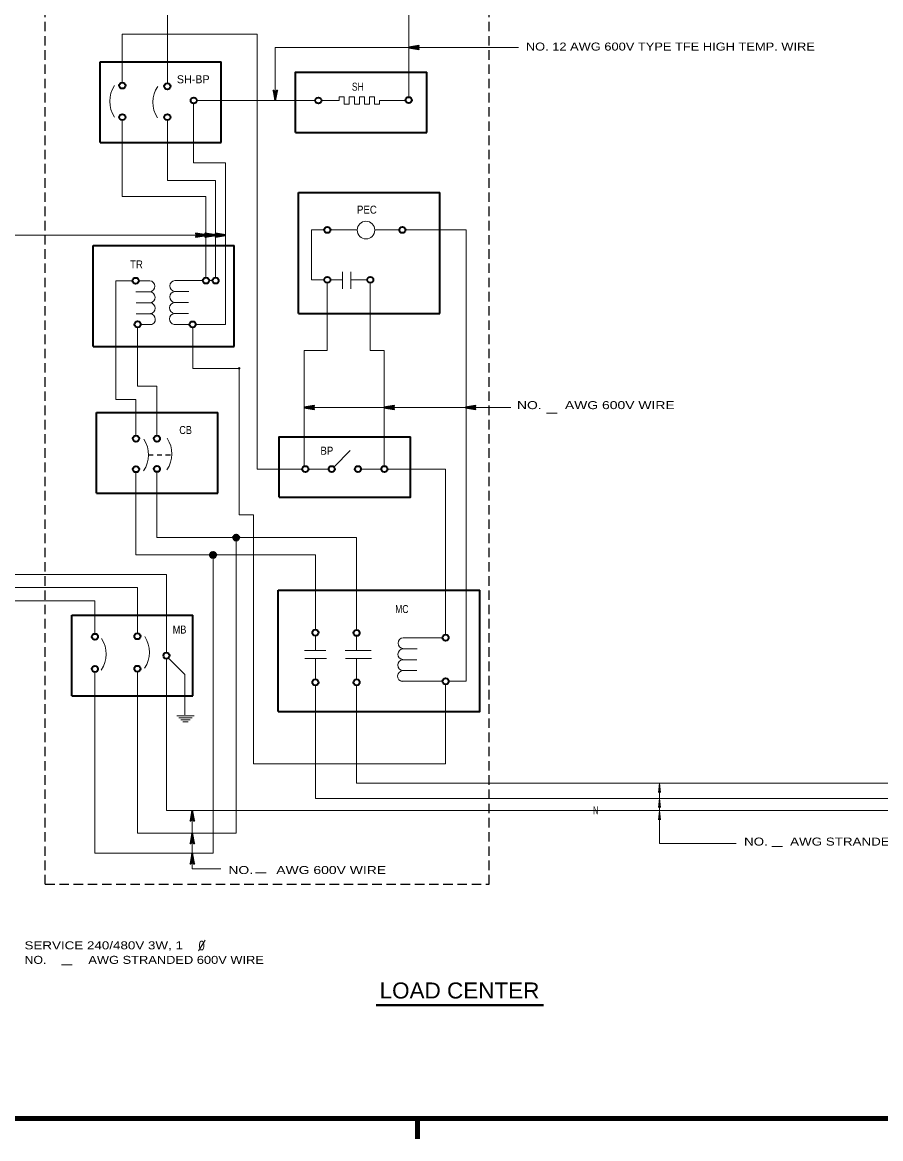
# Model space of a CAD drawing. Extents: x 312583 to 312853, y 144420 to 144585.
# Drawn here: x 312689.8 to 312771.3, y 144421.2 to 144527.2 of the extents above; entities that cross this region are included whole.
import ezdxf
from ezdxf.enums import TextEntityAlignment as Align

# ---------------------------------------------------------------- set-up
doc = ezdxf.new("R2010")
doc.units = 0
doc.header["$LTSCALE"] = 0.3
doc.header["$PDMODE"] = 32
doc.header["$PDSIZE"] = 0.15
doc.linetypes.add('MEDIUM_DASHED', pattern=[4.5, 3, -1.5])
doc.linetypes.add('SHORT_DASHED', pattern=[2.7, 1.5, -1.2])
doc.layers.add('1', color=7, linetype='Continuous', lineweight=13)

msp = doc.modelspace()

# ---------------------------------------------------------------- linework, layer by layer
at = {"layer": '1', "linetype": 'MEDIUM_DASHED', "lineweight": 25}
for p, q in [((312691.9957, 144445.3243), (312691.9957, 144533.491)), ((312734.1624, 144445.3243), (312734.1624, 144533.491)), ((312691.9957, 144445.3243), (312734.1624, 144445.3243))]:
    msp.add_line(p, q, dxfattribs=at)
at = {"layer": '1'}
for p, q in [((312703.5954, 144529.466), (312703.5954, 144521.4006)), ((312726.511, 144529.466), (312726.511, 144520.0896)), ((312699.3174, 144526.0543), (312712.1284, 144526.0543)), ((312699.3174, 144526.0543), (312699.3174, 144521.4773)), ((312712.1284, 144526.0543), (312712.1284, 144484.754)), ((312726.511, 144524.7816), (312736.9343, 144524.7816)), ((312719.91, 144519.7523), (312719.91, 144520.1126)), ((312719.91, 144520.1126), (312720.393, 144520.1126)), ((312720.393, 144519.392), (312720.393, 144520.1126)), ((312720.8684, 144519.392), (312720.8684, 144520.1126)), ((312720.8684, 144520.1126), (312721.3514, 144520.1126)), ((312721.3514, 144519.392), (312721.3514, 144520.1126)), ((312721.8267, 144519.392), (312721.8267, 144520.1126)), ((312721.8267, 144520.1126), (312722.3097, 144520.1126)), ((312722.3097, 144519.392), (312722.3097, 144520.1126)), ((312722.785, 144519.392), (312722.785, 144520.1126)), ((312722.785, 144520.1126), (312723.268, 144520.1126)), ((312723.268, 144519.392), (312723.268, 144520.1126)), ((312706.3937, 144519.7523), (312717.587, 144519.7523)), ((312718.2234, 144519.7523), (312719.91, 144519.7523)), ((312720.393, 144519.392), (312720.8684, 144519.392)), ((312721.3514, 144519.392), (312721.8267, 144519.392)), ((312722.3097, 144519.392), (312722.785, 144519.392)), ((312723.268, 144519.392), (312723.7434, 144519.392)), ((312723.7434, 144519.392), (312723.7434, 144519.7523)), ((312723.7434, 144519.7523), (312726.235, 144519.7523)), ((312699.3174, 144517.874), (312699.3174, 144510.652)), ((312703.5954, 144517.9046), (312703.5954, 144512.1623)), ((312703.5954, 144512.1623), (312708.1724, 144512.1623)), ((312708.1724, 144512.1623), (312708.1724, 144502.9623)), ((312699.3174, 144510.652), (312707.26, 144510.652)), ((312707.26, 144510.652), (312707.26, 144502.9776)), ((312717.288, 144507.4626), (312717.288, 144502.7246)), ((312718.461, 144507.4626), (312717.288, 144507.4626)), ((312721.6197, 144507.4626), (312719.0667, 144507.4626)), ((312725.6217, 144507.4626), (312723.291, 144507.4626)), ((312731.962, 144507.4626), (312726.2197, 144507.4626)), ((312731.962, 144464.5983), (312731.962, 144507.4626)), ((312708.1647, 144506.9566), (312709.1307, 144506.9566)), ((312720.2167, 144501.866), (312720.2167, 144503.476)), ((312721.0217, 144501.866), (312721.0217, 144503.476)), ((312698.6887, 144502.6326), (312698.6887, 144491.3703)), ((312700.291, 144502.6326), (312698.6887, 144502.6326)), ((312701.924, 144502.6326), (312700.866, 144502.6326)), ((312704.316, 144502.6556), (312706.961, 144502.6556)), ((312707.5054, 144502.6556), (312707.881, 144502.6556)), ((312717.288, 144502.7246), (312718.4917, 144502.7246)), ((312718.76, 144502.441), (312718.76, 144496.001)), ((312719.059, 144502.7246), (312720.2167, 144502.7246)), ((312721.0217, 144502.7246), (312722.5627, 144502.7246)), ((312722.8617, 144502.4256), (312722.8617, 144496.001)), ((312701.9547, 144501.59), (312700.613, 144501.59)), ((312701.9394, 144501.59), (312700.613, 144501.59)), ((312704.2854, 144501.613), (312705.627, 144501.613)), ((312704.3007, 144501.613), (312705.627, 144501.613)), ((312701.97, 144500.5473), (312700.6284, 144500.5473)), ((312701.9547, 144500.5473), (312700.6284, 144500.5473)), ((312704.27, 144500.5703), (312705.6117, 144500.5703)), ((312704.2854, 144500.5703), (312705.6117, 144500.5703)), ((312701.9854, 144499.5046), (312700.6437, 144499.5046)), ((312701.97, 144499.5046), (312700.6437, 144499.5046)), ((312704.2547, 144499.5276), (312705.5964, 144499.5276)), ((312704.27, 144499.5276), (312705.5964, 144499.5276)), ((312702.108, 144498.4926), (312701.0577, 144498.4926)), ((312704.2394, 144498.485), (312705.581, 144498.485)), ((312709.1307, 144498.485), (312706.2787, 144498.485)), ((312722.8617, 144496.001), (312724.188, 144496.001)), ((312724.188, 144485.0223), (312724.188, 144496.001)), ((312702.5987, 144492.6276), (312702.5987, 144487.928)), ((312698.6887, 144491.3703), (312700.613, 144491.3703)), ((312700.613, 144491.3703), (312700.613, 144487.9126)), ((312724.1574, 144490.6113), (312716.575, 144490.6113)), ((312739.5827, 144490.0516), (312740.6177, 144490.0516)), ((312719.4194, 144484.9763), (312720.9527, 144486.5096)), ((312700.613, 144484.4243), (312700.613, 144476.6043)), ((312702.5987, 144484.4933), (312702.5987, 144478.245)), ((312712.1284, 144484.754), (312716.3987, 144484.754)), ((312716.9584, 144484.754), (312718.898, 144484.754)), ((312721.9494, 144484.754), (312723.9044, 144484.754)), ((312724.5177, 144484.754), (312730.007, 144484.754)), ((312730.007, 144484.754), (312730.007, 144468.9836)), ((312710.1274, 144478.245), (312710.1274, 144450.185)), ((312721.5584, 144478.245), (312721.5584, 144469.5356)), ((312700.613, 144476.6043), (312717.656, 144476.6043)), ((312707.9347, 144476.6043), (312707.9347, 144448.2913)), ((312717.656, 144476.6043), (312717.656, 144469.4743)), ((312703.511, 144474.7566), (312672.6987, 144474.7566)), ((312703.511, 144474.7566), (312703.511, 144467.32)), ((312700.751, 144473.4916), (312675.9417, 144473.4916)), ((312700.751, 144469.1906), (312700.751, 144473.4916)), ((312696.7184, 144472.2266), (312678.7324, 144472.2266)), ((312696.7184, 144469.114), (312696.7184, 144472.2266)), ((312717.656, 144468.93), (312717.656, 144467.5193)), ((312721.5584, 144468.93), (312721.5584, 144467.5193)), ((312725.9897, 144468.7383), (312729.6774, 144468.7383)), ((312716.6287, 144467.5193), (312718.6374, 144467.5193)), ((312720.4774, 144467.5193), (312722.9537, 144467.5193)), ((312725.959, 144467.6956), (312727.3007, 144467.6956)), ((312725.9744, 144467.6956), (312727.3007, 144467.6956)), ((312703.511, 144466.7603), (312703.511, 144452.3163)), ((312705.259, 144465.2423), (312703.6797, 144466.8216)), ((312716.6517, 144466.7756), (312718.6987, 144466.7756)), ((312717.656, 144466.7756), (312717.656, 144464.79)), ((312720.508, 144466.7756), (312722.9767, 144466.7756)), ((312721.5584, 144466.7756), (312721.5584, 144464.8206)), ((312725.9437, 144466.653), (312727.2854, 144466.653)), ((312725.959, 144466.653), (312727.2854, 144466.653)), ((312696.7184, 144448.2913), (312696.7184, 144465.4646)), ((312700.751, 144450.185), (312700.751, 144465.4646)), ((312705.259, 144465.2423), (312705.259, 144461.4166)), ((312725.9284, 144465.6103), (312727.27, 144465.6103)), ((312725.9437, 144465.6103), (312727.27, 144465.6103)), ((312717.656, 144464.1843), (312717.656, 144453.4816)), ((312721.5584, 144464.1536), (312721.5584, 144454.9153)), ((312725.8057, 144464.5983), (312729.708, 144464.5983)), ((312730.007, 144456.7553), (312730.007, 144464.2993)), ((312730.3367, 144464.5983), (312731.962, 144464.5983)), ((312704.4924, 144461.3246), (312706.1407, 144461.3246)), ((312704.684, 144461.133), (312705.949, 144461.133)), ((312704.8757, 144460.9336), (312705.7574, 144460.9336)), ((312705.0674, 144460.742), (312705.5657, 144460.742)), ((312711.768, 144456.7553), (312730.007, 144456.7553)), ((312721.5584, 144454.9153), (312776.954, 144454.9153)), ((312750.3234, 144454.9153), (312750.216, 144454.049)), ((312750.216, 144454.049), (312750.3234, 144454.325)), ((312750.3234, 144454.9153), (312750.4307, 144454.049)), ((312750.4307, 144454.049), (312750.3234, 144454.325)), ((312750.3234, 144453.474), (312750.216, 144452.6076)), ((312750.3234, 144453.474), (312750.4307, 144452.6076)), ((312703.511, 144452.3163), (312737.4437, 144452.3163)), ((312705.9644, 144450.162), (312705.9644, 144452.3163)), ((312721.6236, 144452.3163), (312795.6913, 144452.3163)), ((312750.216, 144452.6076), (312750.3234, 144452.8836)), ((312750.3234, 144452.3086), (312750.216, 144451.4423)), ((312750.4307, 144452.6076), (312750.3234, 144452.8836)), ((312750.3234, 144452.3086), (312750.4307, 144451.4423)), ((312750.216, 144451.4423), (312750.3234, 144451.7183)), ((312750.4307, 144451.4423), (312750.3234, 144451.7183)), ((312710.1274, 144450.185), (312700.751, 144450.185)), ((312757.599, 144449.1883), (312750.3234, 144449.1883)), ((312760.9877, 144448.9046), (312761.992, 144448.9046)), ((312707.9347, 144448.2913), (312696.7184, 144448.2913)), ((312708.663, 144446.7886), (312705.9644, 144446.7886)), ((312711.9674, 144446.4206), (312712.9717, 144446.4206)), ((312707.1895, 144440.0218), (312706.5531, 144439.0021)), ((312693.529, 144437.6576), (312694.564, 144437.6576))]:
    msp.add_line(p, q, dxfattribs=at)
at = {"layer": '1', "lineweight": 35}
for p, q in [((312697.2167, 144523.44), (312708.7167, 144523.44)), ((312697.2167, 144515.7733), (312697.2167, 144523.44)), ((312708.7167, 144515.7733), (312708.7167, 144523.44)), ((312728.2284, 144516.7086), (312728.2284, 144522.4586)), ((312697.2167, 144515.7733), (312708.7167, 144515.7733)), ((312715.77, 144516.7086), (312728.2284, 144516.7086)), ((312716.0614, 144511.0276), (312729.478, 144511.0276)), ((312716.0614, 144499.5276), (312716.0614, 144511.0276)), ((312729.478, 144499.5276), (312729.478, 144511.0276)), ((312696.5344, 144505.9753), (312709.951, 144505.9753)), ((312696.5344, 144496.392), (312696.5344, 144505.9753)), ((312709.951, 144496.392), (312709.951, 144505.9753)), ((312716.0614, 144499.5276), (312729.478, 144499.5276)), ((312696.5344, 144496.392), (312709.951, 144496.392)), ((312696.8717, 144490.1283), (312708.3717, 144490.1283)), ((312696.8717, 144482.4616), (312696.8717, 144490.1283)), ((312708.3717, 144482.4616), (312708.3717, 144490.1283)), ((312696.8717, 144482.4616), (312708.3717, 144482.4616)), ((312714.1064, 144473.2463), (312733.273, 144473.2463)), ((312714.1064, 144461.7463), (312714.1064, 144473.2463)), ((312694.5257, 144470.8773), (312706.0257, 144470.8773)), ((312694.5257, 144463.2106), (312694.5257, 144470.8773)), ((312706.0257, 144463.2106), (312706.0257, 144470.8773)), ((312694.5257, 144463.2106), (312706.0257, 144463.2106))]:
    msp.add_line(p, q, dxfattribs=at)
at = {"layer": '1', "linetype": 'SHORT_DASHED', "lineweight": 25}
msp.add_line((312701.809, 144486.0956), (312703.994, 144486.0956), dxfattribs=at)
at = {"layer": '1', "lineweight": 40}
msp.add_line((312723.4358, 144433.8433), (312739.3103, 144433.8433), dxfattribs=at)
at = {"layer": '1', "lineweight": 158}
for p, q in [((312616.5, 144423.0846), (312849, 144423.0846)), ((312727.35, 144421.1646), (312727.35, 144423.0846))]:
    msp.add_line(p, q, dxfattribs=at)
at = {"layer": '1'}
for points in [[(312726.511, 144524.7816), (312713.8457, 144524.7816), (312713.8457, 144519.7523)], [(312706.0794, 144519.4226), (312706.0794, 144513.8413), (312709.1307, 144513.8413), (312709.1307, 144498.485)], [(312688.4557, 144506.9566), (312707.2677, 144506.9566), (312708.1647, 144506.9566)], [(312700.7664, 144498.2013), (312700.7664, 144492.6276), (312702.5987, 144492.6276)], [(312706.0104, 144498.2013), (312706.0104, 144494.3143), (312710.411, 144494.3143)], [(312716.575, 144484.961), (312716.575, 144496.001), (312718.76, 144496.001)], [(312710.411, 144494.3143), (312710.411, 144480.407), (312711.768, 144480.407), (312711.768, 144456.7553)], [(312736.217, 144490.6113), (312731.893, 144490.6113), (312724.1574, 144490.6113)], [(312702.5987, 144478.245), (312708.3104, 144478.245), (312721.5584, 144478.245)], [(312750.3234, 144449.1883), (312750.3234, 144452.3086), (312750.3234, 144453.474), (312750.3234, 144454.9153)], [(312717.656, 144453.4816), (312744.0946, 144453.4816), (312778.9166, 144453.4816)], [(312705.9644, 144446.7886), (312705.9644, 144448.2376), (312705.9644, 144450.162)]]:
    msp.add_lwpolyline(points, dxfattribs=at)
at = {"layer": '1', "lineweight": 35}
for points in [[(312726.511, 144524.7816), (312727.477, 144524.6206), (312727.155, 144524.7816), (312727.477, 144524.9426)], [(312713.8457, 144519.7523), (312714.0067, 144520.7183), (312713.8457, 144520.3963), (312713.6847, 144520.7183)], [(312707.2677, 144506.9566), (312706.3017, 144507.1176), (312706.6237, 144506.9566), (312706.3017, 144506.7956)], [(312708.1647, 144506.9566), (312707.1987, 144507.1176), (312707.5207, 144506.9566), (312707.1987, 144506.7956)], [(312709.1307, 144506.9566), (312708.1647, 144507.1176), (312708.4867, 144506.9566), (312708.1647, 144506.7956)], [(312716.575, 144490.6113), (312717.541, 144490.4503), (312717.219, 144490.6113), (312717.541, 144490.7723)], [(312724.1574, 144490.6113), (312725.1234, 144490.4503), (312724.8014, 144490.6113), (312725.1234, 144490.7723)], [(312731.893, 144490.6113), (312732.859, 144490.4503), (312732.537, 144490.6113), (312732.859, 144490.7723)], [(312705.9644, 144452.3163), (312705.8034, 144451.3503), (312705.9644, 144451.6723), (312706.1254, 144451.3503)], [(312705.9644, 144450.162), (312705.8034, 144449.196), (312705.9644, 144449.518), (312706.1254, 144449.196)], [(312705.9644, 144448.2376), (312705.8034, 144447.2716), (312705.9644, 144447.5936), (312706.1254, 144447.2716)]]:
    msp.add_lwpolyline(points, close=True, dxfattribs=at)
for points in [[(312715.77, 144516.7086), (312715.77, 144522.4586), (312728.2284, 144522.4586)], [(312714.2214, 144482.0783), (312714.2214, 144487.8283), (312726.6797, 144487.8283)], [(312714.2214, 144482.0783), (312726.6797, 144482.0783), (312726.6797, 144487.8283)], [(312714.1064, 144461.7463), (312733.273, 144461.7463), (312733.273, 144473.2463)]]:
    msp.add_lwpolyline(points, dxfattribs=at)
for centre, radius in [((312699.3171, 144521.1706), 0.2897), ((312703.5951, 144521.1016), 0.2897), ((312706.1024, 144519.7525), 0.2897), ((312717.932, 144519.7521), 0.2897), ((312726.5108, 144519.7906), 0.2897), ((312699.3176, 144518.173), 0.2897), ((312703.5956, 144518.173), 0.2897), ((312718.783, 144507.4624), 0.2897), ((312725.913, 144507.4629), 0.2897), ((312707.2598, 144502.6556), 0.2897), ((312708.1721, 144502.6556), 0.2897), ((312718.783, 144502.7244), 0.2897), ((312722.8617, 144502.7244), 0.2897), ((312700.5824, 144502.6329), 0.2897), ((312700.7664, 144498.4929), 0.2897), ((312705.9874, 144498.4852), 0.2897), ((312700.6128, 144487.6443), 0.2897), ((312702.5985, 144487.6443), 0.2897), ((312700.6133, 144484.7386), 0.2897), ((312702.5989, 144484.7693), 0.2897), ((312716.6977, 144484.7542), 0.2897), ((312719.2047, 144484.7542), 0.2897), ((312721.6887, 144484.7542), 0.2897), ((312724.2034, 144484.7542), 0.2897), ((312710.1276, 144478.245), 0.2897), ((312710.1274, 144478.245), 0.23), ((312710.1274, 144478.245), 0.1533), ((312710.1274, 144478.245), 0.0767), ((312707.9349, 144476.6043), 0.2897), ((312707.9347, 144476.6043), 0.23), ((312707.9347, 144476.6043), 0.1533), ((312707.9347, 144476.6043), 0.0767), ((312696.7181, 144468.8303), 0.2897), ((312700.7508, 144468.8763), 0.2897), ((312717.6558, 144469.2213), 0.2897), ((312721.5581, 144469.1983), 0.2897), ((312730.0068, 144468.7383), 0.2897), ((312703.5113, 144467.0363), 0.2897), ((312696.7186, 144465.7713), 0.2897), ((312700.7513, 144465.7866), 0.2897), ((312717.6563, 144464.4986), 0.2897), ((312721.5586, 144464.4986), 0.2897), ((312730.0073, 144464.5983), 0.2897)]:
    msp.add_circle(centre, radius, dxfattribs=at)
at = {"layer": '1'}
msp.add_circle((312722.4554, 144507.4473), 0.8385, dxfattribs=at)
for centre, radius, start, end in [((312700.8046, 144519.6642), 2.6791, 145.78717, 213.62519), ((312704.8909, 144519.5876), 2.6791, 145.78717, 213.62519), ((312701.8862, 144502.1127), 0.5203, 277.35858, 85.77701), ((312704.3539, 144502.1357), 0.5203, 94.22299, 262.64142), ((312701.9015, 144501.07), 0.5203, 277.35858, 85.77701), ((312704.3385, 144501.093), 0.5203, 94.22299, 262.64142), ((312701.9169, 144500.0273), 0.5203, 277.35858, 85.77701), ((312704.3232, 144500.0503), 0.5203, 94.22299, 262.64142), ((312701.9322, 144498.9847), 0.5203, 277.35858, 85.77701), ((312704.3079, 144499.0077), 0.5203, 94.22299, 262.64142), ((312699.1258, 144486.0994), 2.6791, 325.78717, 33.62519), ((312701.3415, 144486.1914), 2.6791, 325.78717, 33.62519), ((312695.1085, 144467.178), 2.6791, 325.78717, 33.62519), ((312699.2178, 144467.3544), 2.6791, 325.78717, 33.62519), ((312726.0275, 144468.2183), 0.5203, 94.22299, 262.64142), ((312726.0122, 144467.1757), 0.5203, 94.22299, 262.64142), ((312725.9969, 144466.133), 0.5203, 94.22299, 262.64142), ((312725.9815, 144465.0903), 0.5203, 94.22299, 262.64142)]:
    msp.add_arc(centre, radius, start, end, dxfattribs=at)
msp.add_point((312710.411, 144494.3143), dxfattribs=at)

# ---------------------------------------------------------------- texts
for s, height, width, p in [('NO. 12 AWG 600V TYPE TFE HIGH TEMP. WIRE', 0.76, 1.2, (312737.6337, 144524.4951)), ('SH', 0.76, 0.8, (312721.1126, 144520.6827)), ('PEC', 0.76, 0.9, (312721.6018, 144509.0064)), ('TR', 0.76, 0.9, (312700.0528, 144503.8046)), ('NO.      AWG 600V WIRE', 0.76, 1.3, (312736.792, 144490.4455)), ('CB', 0.76, 0.85, (312704.7291, 144488.0803)), ('BP', 0.76, 0.9, (312718.1319, 144486.1158)), ('MC', 0.76, 0.8, (312725.2298, 144471.0776)), ('MB', 0.76, 0.85, (312704.1061, 144469.1312)), ('NO.      AWG STRANDED 600V WIRE', 0.76, 1.25, (312758.352, 144448.9976)), ('NO.      AWG 600V WIRE', 0.76, 1.3, (312709.3878, 144446.2951)), ('SERVICE 240/480V 3W, 1', 0.76, 1.25, (312690.033, 144439.144)), ('NO.     ', 0.76, 1.15, (312690.033, 144437.764)), ('  AWG STRANDED 600V WIRE', 0.76, 1.2, (312695.415, 144437.764)), ('LOAD CENTER', 1.52, 1.05, (312723.7446, 144434.478))]:
    msp.add_text(s, height=height, dxfattribs=dict(at, width=width)).set_placement(p)
msp.add_text('SH-BP', height=0.76, dxfattribs=at).set_placement((312704.498, 144521.3901))
at = {"layer": '1', "width": 0.65}
msp.add_text('N', height=0.76, rotation=180, dxfattribs=at).set_placement((312744.5213, 144452.7275))
at = {"layer": '1', "width": 0.85}
msp.add_text('0', height=0.92, rotation=180, dxfattribs=at).set_placement((312706.8521, 144439.9681), align=Align.CENTER)

doc.saveas('drawing.dxf')
